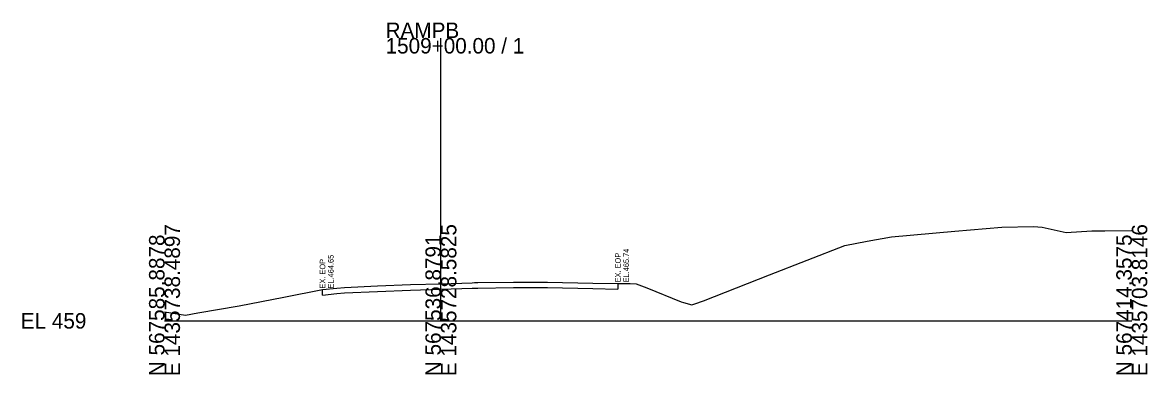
# Model space of a CAD drawing. Extents: x 1431908 to 1449087, y 567604 to 577825.
# Drawn here: x 1440484.4 to 1440688, y 575548.6 to 575612.3 of the extents above; entities that cross this region are included whole.
import ezdxf

# ---------------------------------------------------------------- set-up
doc = ezdxf.new("R2010")
doc.units = 0
for name, color, linetype in [('DESIGN - SHEET - Light Grid', 7, 'Continuous'), ('SURVEY - GROUND - Existing Pavement Layer', 7, 'Continuous'), ('SURVEY - GROUND - Existing Pavement Text', 7, 'Continuous'), ('SURVEY - GROUND - Top of Ground', 7, 'Continuous')]:
    doc.layers.add(name, color=color, linetype=linetype)

msp = doc.modelspace()

# ---------------------------------------------------------------- linework, layer by layer
at = {"layer": 'DESIGN - SHEET - Light Grid'}
for p, q in [((1440560.12, 575558.33), (1440560.12, 575609.45)), ((1440510.12, 575558.33), (1440560.12, 575558.33)), ((1440560.12, 575558.33), (1440685.12, 575558.33))]:
    msp.add_line(p, q, dxfattribs=at)
at = {"layer": 'SURVEY - GROUND - Existing Pavement Layer'}
for p, q in [((1440538.71, 575562.98), (1440538.71, 575563.98)), ((1440548.63, 575563.63), (1440554.65, 575563.88)), ((1440554.65, 575563.88), (1440560.12, 575564.05)), ((1440560.12, 575564.05), (1440565.77, 575564.23)), ((1440565.77, 575564.23), (1440566.23, 575564.25)), ((1440566.23, 575564.25), (1440566.8, 575564.25)), ((1440566.8, 575564.25), (1440573.27, 575564.33)), ((1440573.27, 575564.33), (1440575.75, 575564.33)), ((1440575.75, 575564.33), (1440579.43, 575564.34)), ((1440579.43, 575564.34), (1440587.59, 575564.17)), ((1440587.59, 575564.17), (1440592.15, 575564.08)), ((1440592.15, 575565.08), (1440592.15, 575564.08)), ((1440538.71, 575562.98), (1440541.32, 575563.25)), ((1440541.32, 575563.25), (1440542.69, 575563.38)), ((1440542.69, 575563.38), (1440548.63, 575563.63))]:
    msp.add_line(p, q, dxfattribs=at)
at = {"layer": 'SURVEY - GROUND - Top of Ground'}
msp.add_lwpolyline([(1440510.12, 575559.95), (1440513.9, 575559.37), (1440516.13, 575559.75), (1440523.65, 575561.06), (1440531.71, 575562.63), (1440538.71, 575563.98), (1440541.32, 575564.25), (1440542.69, 575564.38), (1440548.63, 575564.63), (1440554.65, 575564.88), (1440560.12, 575565.05), (1440565.77, 575565.23), (1440566.23, 575565.25), (1440566.8, 575565.25), (1440573.27, 575565.33), (1440575.75, 575565.33), (1440579.43, 575565.34), (1440587.59, 575565.17), (1440592.15, 575565.08), (1440594.37, 575565.06), (1440595.47, 575565.04), (1440597.39, 575564.29), (1440603.61, 575561.76), (1440604.02, 575561.65), (1440605.5, 575561.24), (1440606.06, 575561.43), (1440607.63, 575561.97), (1440619.55, 575566.63), (1440633.19, 575571.93), (1440637.25, 575572.71), (1440641.66, 575573.52), (1440653.13, 575574.56), (1440661.61, 575575.24), (1440667.33, 575575.37), (1440668.91, 575575.24), (1440673.27, 575574.32), (1440677.89, 575574.59), (1440678.31, 575574.61), (1440680.24, 575574.62), (1440685.09, 575574.65), (1440685.12, 575574.65)], dxfattribs=at)

# ---------------------------------------------------------------- texts
at = {"layer": 'DESIGN - SHEET - Light Grid'}
for s, p in [('RAMPB', (1440550.12, 575609.45)), ('1509+00.00 / 1', (1440550.12, 575606.65)), ('EL 459', (1440484.12, 575556.93))]:
    msp.add_text(s, height=2.8, dxfattribs=at).set_placement(p)
for s, p in [('E 1435738.4897', (1440512.92, 575548.33)), ('E 1435728.5825', (1440562.92, 575548.33)), ('E 1435703.8146', (1440687.92, 575548.33)), ('N 567585.8878', (1440510.12, 575548.33)), ('N 567536.8791', (1440560.12, 575548.33)), ('N 567414.3575', (1440685.12, 575548.33))]:
    msp.add_text(s, height=2.8, rotation=90, dxfattribs=at).set_placement(p)
at = {"layer": 'SURVEY - GROUND - Existing Pavement Text'}
for s, p in [('EL.464.65', (1440540.71, 575564.18)), ('EX. EOP', (1440592.65, 575565.28)), ('EL.465.74', (1440594.15, 575565.28)), ('EX. EOP', (1440539.21, 575564.18))]:
    msp.add_text(s, height=1, rotation=90, dxfattribs=at).set_placement(p)

doc.saveas('drawing.dxf')
